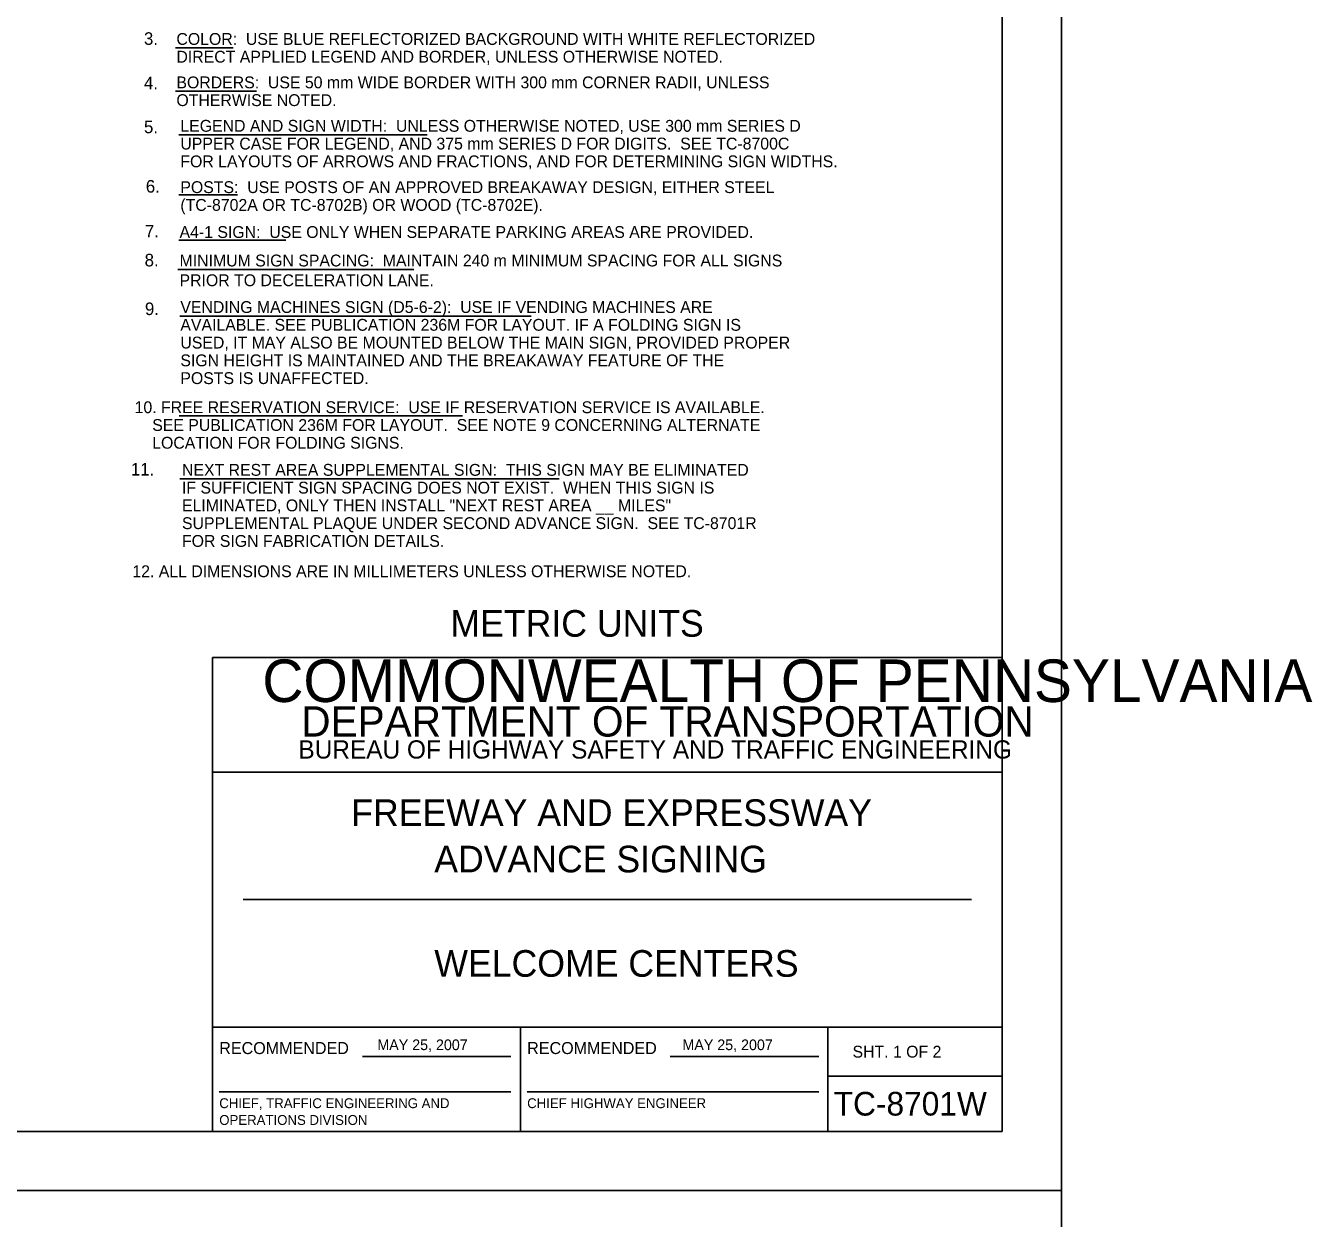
# Model space of a CAD drawing. Extents: x 638689 to 652291, y 298458 to 299646.
# Drawn here: x 651965 to 652290.9, y 299044.7 to 299346.8 of the extents above; entities that cross this region are included whole.
import ezdxf

# ---------------------------------------------------------------- set-up
doc = ezdxf.new("R2010")
doc.units = 0
for name, color, linetype in [('1', 7, 'Continuous'), ('2', 7, 'Continuous'), ('PLT-BNDY', 7, 'Continuous')]:
    doc.layers.add(name, color=color, linetype=linetype)

msp = doc.modelspace()

# ---------------------------------------------------------------- linework, layer by layer
at = {"layer": '1'}
for p, q in [((652212.31, 299066.75), (652212.31, 299630.75)), ((652012.31, 299066.75), (652012.31, 299186.75)), ((652012.31, 299186.75), (652212.31, 299186.75)), ((652212.31, 299157.75), (652012.31, 299157.75)), ((652020.06, 299125.43), (652204.56, 299125.43)), ((652012.31, 299093.12), (652212.31, 299093.12)), ((652090.31, 299093.12), (652090.31, 299066.75)), ((652168.19, 299066.75), (652168.19, 299093.12)), ((652050.24, 299085.69), (652087.87, 299085.69)), ((652128.24, 299085.69), (652165.87, 299085.69)), ((652168.19, 299080.75), (652212.31, 299080.75)), ((652013.99, 299076.8), (652087.87, 299076.8)), ((652091.99, 299076.8), (652165.87, 299076.8)), ((652212.31, 299066.75), (651426.31, 299066.75)), ((651426.31, 299066.75), (652012.31, 299066.75))]:
    msp.add_line(p, q, dxfattribs=at)
at = {"layer": '2'}
for p, q in [((652002.92, 299341.19), (652017.54, 299341.19)), ((652002.9, 299330.19), (652023.44, 299330.19)), ((652003.76, 299319.15), (652066.64, 299319.15)), ((652003.76, 299303.96), (652018.61, 299303.96)), ((652003.78, 299292.49), (652030.86, 299292.49)), ((652003.52, 299285.03), (652063.3, 299285.03)), ((652004.01, 299273.24), (652092.98, 299273.24)), ((652003.84, 299247.98), (652075.64, 299247.98)), ((652004.02, 299232), (652100.07, 299232))]:
    msp.add_line(p, q, dxfattribs=at)
at = {"layer": 'PLT-BNDY'}
for points in [[(651386.31, 299645.75), (652227.31, 299645.75), (652227.31, 299051.75), (651386.31, 299051.75)], [(651386.31, 299051.75), (652227.31, 299051.75), (652227.31, 298457.75), (651386.31, 298457.75)]]:
    msp.add_lwpolyline(points, close=True, dxfattribs=at)

# ---------------------------------------------------------------- texts
at = {"layer": '1'}
for s, height, p in [('COMMONWEALTH OF PENNSYLVANIA', 10.7828, (652024.9, 299175.48)), ('DEPARTMENT OF TRANSPORTATION', 7.6837, (652034.76, 299166.73)), ('BUREAU OF HIGHWAY SAFETY AND TRAFFIC ENGINEERING', 4.6253, (652034.04, 299161.16)), ('FREEWAY AND EXPRESSWAY', 6.75, (652047.42, 299144.09)), ('ADVANCE SIGNING', 6.75, (652068.45, 299132.34)), ('WELCOME CENTERS', 6.75, (652068.47, 299105.9)), ('RECOMMENDED', 3.048, (652013.99, 299086.32)), ('RECOMMENDED', 3.048, (652091.99, 299086.32)), ('SHT. 1 OF 2', 3, (652174.4, 299085.43)), ('CHIEF, TRAFFIC ENGINEERING AND', 2.5, (652013.99, 299072.63)), ('CHIEF HIGHWAY ENGINEER', 2.5, (652091.99, 299072.63)), ('TC-8701W', 6, (652169.64, 299070.75)), ('OPERATIONS DIVISION', 2.5, (652013.99, 299068.38))]:
    msp.add_text(s, height=height, dxfattribs=at).set_placement(p)
at = {"layer": '2'}
for s, height, p in [('3.  ', 3.183, (651994.92, 299341.92)), ('COLOR:  USE BLUE REFLECTORIZED BACKGROUND WITH WHITE REFLECTORIZED', 3, (652003.14, 299341.91)), ('DIRECT APPLIED LEGEND AND BORDER, UNLESS OTHERWISE NOTED.', 3, (652003.14, 299337.41)), ('4.  ', 3.183, (651994.92, 299330.67)), ('BORDERS:  USE 50 mm WIDE BORDER WITH 300 mm CORNER RADII, UNLESS', 3, (652003.14, 299330.91)), ('OTHERWISE NOTED.', 3, (652003.14, 299326.41)), ('5.  ', 3.183, (651994.92, 299319.55)), ('LEGEND AND SIGN WIDTH:  UNLESS OTHERWISE NOTED, USE 300 mm SERIES D', 3, (652004.14, 299319.91)), ('UPPER CASE FOR LEGEND, AND 375 mm SERIES D FOR DIGITS.  SEE TC-8700C', 3, (652004.14, 299315.41)), ('FOR LAYOUTS OF ARROWS AND FRACTIONS, AND FOR DETERMINING SIGN WIDTHS.', 3, (652004.14, 299310.91)), ('6.  ', 3.183, (651995.39, 299304.49)), ('POSTS:  USE POSTS OF AN APPROVED BREAKAWAY DESIGN, EITHER STEEL', 3, (652004.14, 299304.38)), ('(TC-8702A OR TC-8702B) OR WOOD (TC-8702E).', 3, (652004.14, 299299.88)), ('7.  ', 3.183, (651995.17, 299293.15)), ('A4-1 SIGN:  USE ONLY WHEN SEPARATE PARKING AREAS ARE PROVIDED.', 3, (652003.93, 299293.01)), ('8.  ', 3.183, (651995.09, 299285.81)), ('MINIMUM SIGN SPACING:  MAINTAIN 240 m MINIMUM SPACING FOR ALL SIGNS', 3, (652003.93, 299285.8)), ('PRIOR TO DECELERATION LANE.', 3, (652003.93, 299280.8)), ('9.', 3.183, (651995.17, 299273.48)), ('VENDING MACHINES SIGN (D5-6-2):  USE IF VENDING MACHINES ARE', 3, (652004.14, 299274.01)), ('AVAILABLE. SEE PUBLICATION 236M FOR LAYOUT. IF A FOLDING SIGN IS', 3, (652004.14, 299269.51)), ('USED, IT MAY ALSO BE MOUNTED BELOW THE MAIN SIGN, PROVIDED PROPER', 3, (652004.14, 299265.01)), ('SIGN HEIGHT IS MAINTAINED AND THE BREAKAWAY FEATURE OF THE', 3, (652004.14, 299260.51)), ('POSTS IS UNAFFECTED.', 3, (652004.14, 299256.01)), ('10. FREE RESERVATION SERVICE:  USE IF RESERVATION SERVICE IS AVAILABLE.', 3, (651992.55, 299248.64)), ('    SEE PUBLICATION 236M FOR LAYOUT.  SEE NOTE 9 CONCERNING ALTERNATE', 3, (651992.55, 299244.14)), ('    LOCATION FOR FOLDING SIGNS.', 3, (651992.55, 299239.64)), ('11.', 3.183, (651991.61, 299232.85)), ('NEXT REST AREA SUPPLEMENTAL SIGN:  THIS SIGN MAY BE ELIMINATED', 3, (652004.55, 299232.78)), ('IF SUFFICIENT SIGN SPACING DOES NOT EXIST.  WHEN THIS SIGN IS', 3, (652004.55, 299228.28)), ('ELIMINATED, ONLY THEN INSTALL "NEXT REST AREA __ MILES" ', 3, (652004.55, 299223.78)), ('SUPPLEMENTAL PLAQUE UNDER SECOND ADVANCE SIGN.  SEE TC-8701R', 3, (652004.55, 299219.28)), ('FOR SIGN FABRICATION DETAILS.', 3, (652004.55, 299214.78)), ('12. ALL DIMENSIONS ARE IN MILLIMETERS UNLESS OTHERWISE NOTED.', 3, (651991.98, 299207.1)), ('METRIC UNITS', 6.75, (652072.54, 299192.02)), ('MAY 25, 2007', 2.7, (652054.04, 299087.32)), ('MAY 25, 2007', 2.7, (652131.32, 299087.32))]:
    msp.add_text(s, height=height, dxfattribs=at).set_placement(p)

doc.saveas('drawing.dxf')
